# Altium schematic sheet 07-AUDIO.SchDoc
size A4
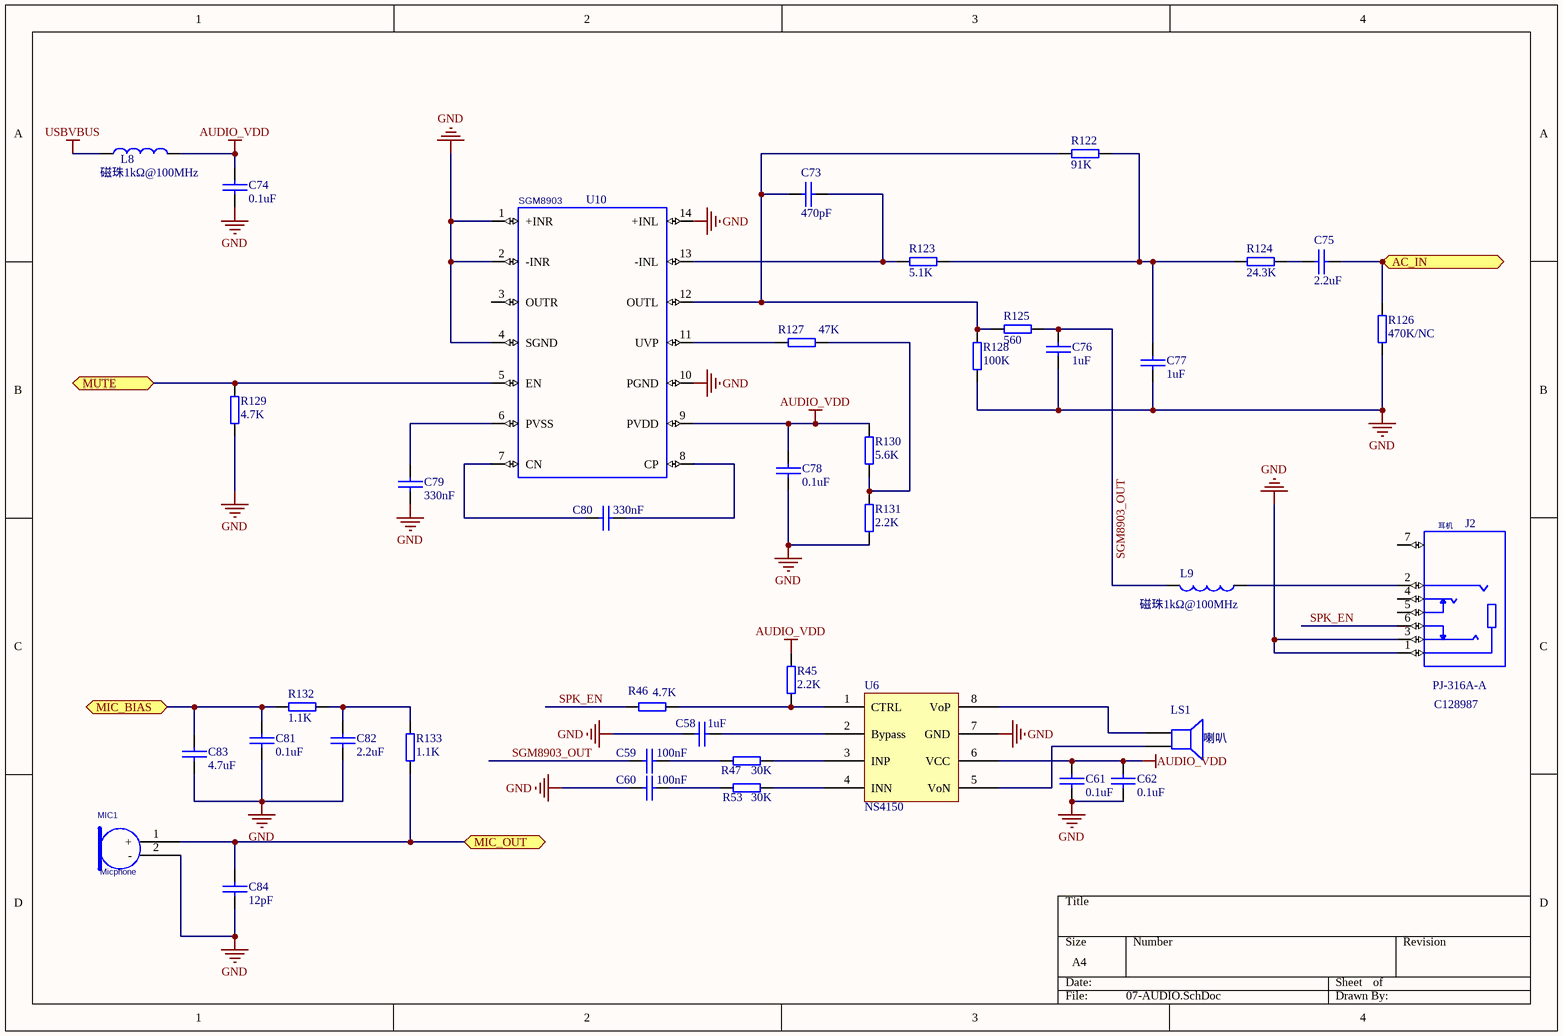
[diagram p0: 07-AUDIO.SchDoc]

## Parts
C58  1uF  [C0402]
C59  100nF  [C0402]
C60  100nF  [C0402]
C61  0.1uF  [C0402]
C62  0.1uF  [C0402]
C73  470pF  [C0402]
C74  0.1uF  [C0402]
C75  2.2uF  [C0402]
C76  1uF  [C0402]
C77  1uF  [C0402]
C78  0.1uF  [C0402]
C79  330nF  [C0402]
C80  330nF  [C0402]
C81  0.1uF  [C0402]
C82  2.2uF  [C0402]
C83  4.7uF  [C0402]
C84  12pF  [C0402]
J2  DEVICE: 耳机  [AUDIO-SMD_PJ-316A-6A]  (hidden comment: MIC6M1_B)
L8  磁珠1kΩ@100MHz  [L0603]
L9  磁珠1kΩ@100MHz  [L0603]
LS1  喇叭  [SPK(2.54)]
MIC1  Micphone  [CAP(2.0,Ф4)]
R45  2.2K  [R0402]
R46  4.7K  [R0402]
R47  30K  [R0402]
R53  30K  [R0402]
R122  91K  [R0402]
R123  5.1K  [R0402]
R124  24.3K  [R0402]
R125  560  [R0402]
R126  470K/NC  [R0402]
R127  47K  [R0402]
R128  100K  [R0402]
R129  4.7K  [R0402]
R130  5.6K  [R0402]
R131  2.2K  [R0402]
R132  1.1K  [R0402]
R133  1.1K  [R0402]
U6  NS4150  [SOP-8M]
U10  SGM8903  [SGM8903]

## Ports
AC_IN (bidir), MIC_BIAS (bidir), MIC_OUT (bidir), MUTE (bidir)

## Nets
AUDIO_VDD: C61.2 C62.2 C74.1 C78.2 L8.2 R45.2 R130.2 U6.6(VCC) U10.9(PVDD)
GND: C58.1 C60.1 C61.1 C62.1 C74.2 C76.1 C77.1 C78.1 C79.1 C81.1 C82.1 C83.1 C84.1 J2.1(P1) J2.3(P3) MIC1.2(-) R126.2 R128.1 R129.1 R131.1 U6.7(GND) U10.1(+INR) U10.2(-INR) U10.4(SGND) U10.10(PGND) U10.14(+INL)
USBVBUS: L8.1
AC_IN: C75.1 R126.1 ; port AC_IN
MIC_BIAS: C81.2 C83.2 R132.2 ; port MIC_BIAS
MIC_OUT: C84.2 MIC1.1(+) R133.2 ; port MIC_OUT
MUTE: R129.2 U10.5(EN) ; port MUTE
SGM8903_OUT: C59.1 C76.2 L9.2 R125.1
SPK_EN: J2.6(P6) R46.2
NetC58_2: C58.2 U6.2(Bypass)
NetC59_2: C59.2 R47.2
NetC60_2: C60.2 R53.2
NetC73_1: C73.1 R123.2 U10.13(-INL)
NetC73_2: C73.2 R122.2 R125.2 R128.2 U10.12(OUTL)
NetC75_2: C75.2 R124.1
NetC77_2: C77.2 R122.1 R123.1 R124.2
NetC79_2: C79.2 U10.6(PVSS)
NetC80_1: C80.1 U10.7(CN)
NetC80_2: C80.2 U10.8(CP)
NetC82_2: C82.2 R132.1 R133.1
NetJ2_2: J2.2(P2) L9.1
NetLS1_1: LS1.1 U6.8(VoP)
NetLS1_2: LS1.2 U6.5(VoN)
NetR45_1: R45.1 R46.1 U6.1(CTRL)
NetR47_1: R47.1 U6.3(INP)
NetR53_1: R53.1 U6.4(INN)
NetR127_1: R127.1 R130.1 R131.2
NetR127_2: R127.2 U10.11(UVP)

Not connected (* = marked no-connect by the designer): J2 4(P4) 5(P5) 7(M1); U10 3(OUTR)

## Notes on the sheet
- (near J2) PJ-316A-A
- (near J2) C128987

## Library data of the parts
C58-C62 C73-C84 = 电容: Capacitor
J2 = MIC6M1_B: PARTS: 1; LEVEL: STD; OriginalSymbolOrigin: (0,0); PKG_TYPE: VAF6-1406E; %208%%161%%192%%224%%195%%251%%179%%198%: 音视频连接器; CODE: 14160153; %195%%232%%202%%246%: 音视频连接器-3.5MM音频连接器-6PIN-弯母-SMT
L8 L9 = 电感: Inductor
MIC1 = Micphone_0: mypage: 13
R45-R47 R53 R122-R133 = 电阻Ω: Resistor
U10 = SGM8903: PARTS: 1; LEVEL: STD; OriginalSymbolOrigin: (0,0)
